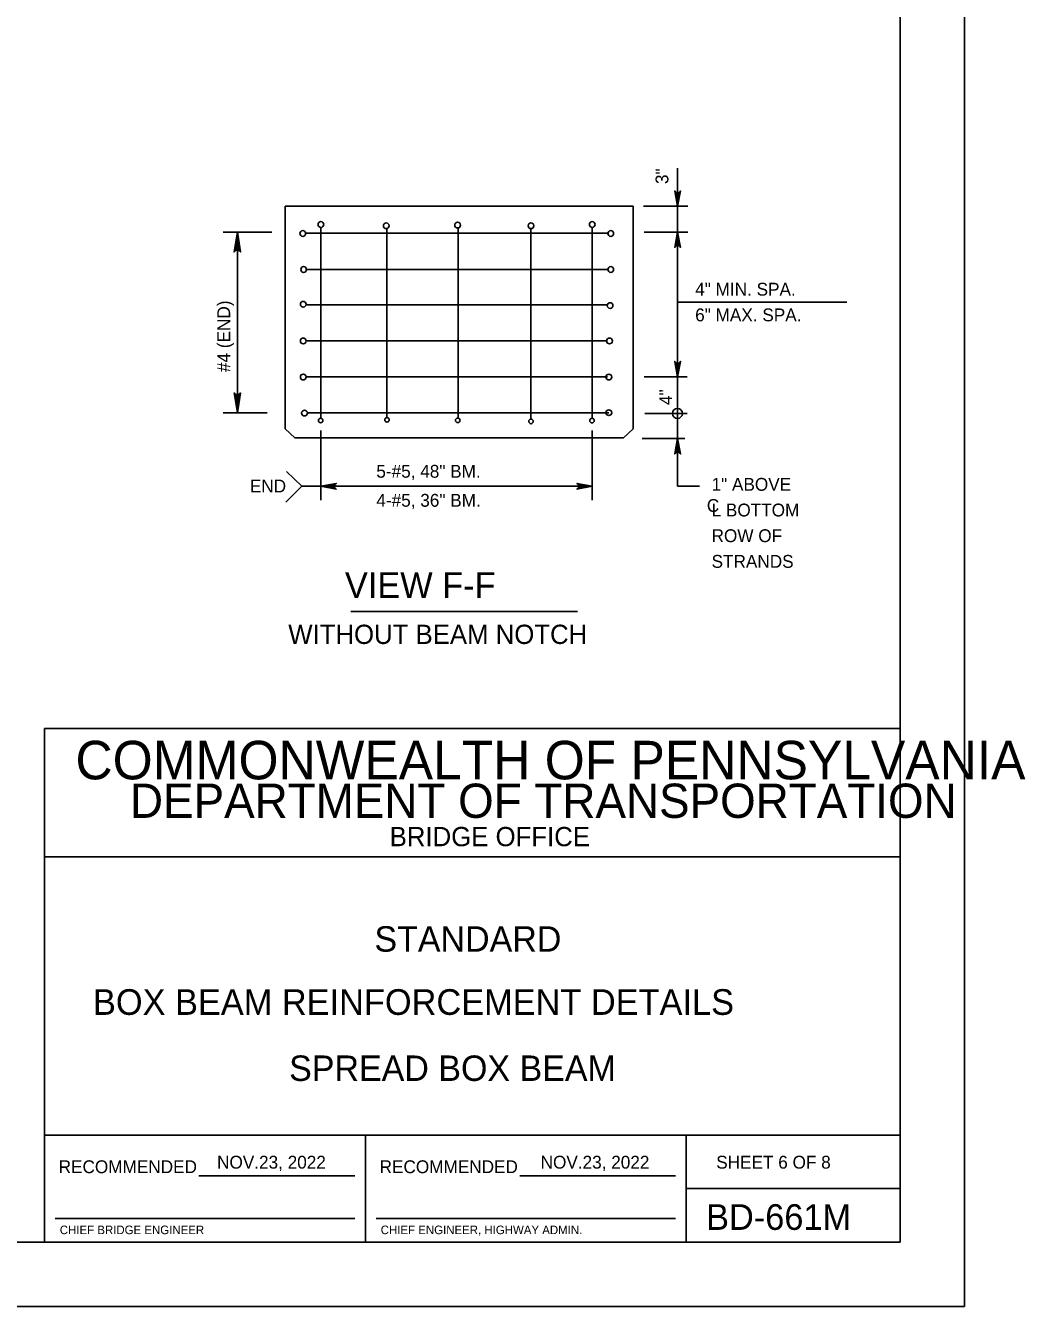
# Model space of a CAD drawing. Extents: x 639331 to 643089, y 299088 to 300975.
# Drawn here: x 642014.7 to 642248.3, y 299087.7 to 299386.9 of the extents above; entities that cross this region are included whole.
import ezdxf

# ---------------------------------------------------------------- set-up
doc = ezdxf.new("R2010")
doc.units = 0
for name, color, linetype in [('1', 7, 'Continuous'), ('DATES', 7, 'Continuous'), ('PLT-BNDY', 7, 'Continuous'), ('SIGNATORY TITLES', 7, 'Continuous')]:
    doc.layers.add(name, color=color, linetype=linetype)

msp = doc.modelspace()

# ---------------------------------------------------------------- linework, layer by layer
at = {"layer": '1'}
for p, q in [((642219.06, 299666.66), (642219.06, 299102.66)), ((642167.03, 299353.53), (642167.03, 299344.35)), ((642156.65, 299344.65), (642075.31, 299344.65)), ((642075.31, 299292.63), (642075.31, 299344.65)), ((642156.65, 299292.63), (642156.65, 299344.65)), ((642159.06, 299344.65), (642169.43, 299344.65)), ((642167.03, 299344.65), (642167.03, 299338.64)), ((642147.07, 299339.69), (642147.07, 299295.19)), ((642072.17, 299338.64), (642060.84, 299338.64)), ((642064.14, 299338.64), (642064.14, 299296.39)), ((642080.09, 299338.34), (642150.94, 299338.34)), ((642083.67, 299339.54), (642083.67, 299295.19)), ((642099.07, 299339.39), (642099.07, 299295.34)), ((642115.76, 299339.54), (642115.76, 299295.19)), ((642132.75, 299339.39), (642132.75, 299295.04)), ((642159.21, 299338.64), (642169.43, 299338.64)), ((642167.03, 299338.64), (642167.03, 299304.81)), ((642080.31, 299329.92), (642150.79, 299329.92)), ((642080.28, 299321.65), (642150.64, 299321.65)), ((642167.03, 299322.27), (642206.54, 299322.27)), ((642080.43, 299313.23), (642150.64, 299313.23)), ((642080.28, 299304.81), (642150.64, 299304.81)), ((642159.21, 299304.81), (642169.28, 299304.81)), ((642167.03, 299304.81), (642167.03, 299296.24)), ((642071.08, 299296.39), (642060.84, 299296.39)), ((642080.43, 299296.39), (642150.94, 299296.39)), ((642159.36, 299296.24), (642169.28, 299296.24)), ((642167.03, 299296.24), (642167.03, 299290.53)), ((642075.31, 299292.63), (642077.57, 299290.53)), ((642083.67, 299292.24), (642083.67, 299275.98)), ((642147.07, 299292.24), (642147.07, 299275.98)), ((642154.4, 299290.53), (642156.65, 299292.63)), ((642154.4, 299290.53), (642077.57, 299290.53)), ((642158.76, 299290.38), (642168.68, 299290.38)), ((642167.03, 299290.53), (642167.03, 299279.25)), ((642079.18, 299279.25), (642075.66, 299282.68)), ((642079.18, 299279.25), (642075.46, 299275.53)), ((642079.18, 299279.25), (642147.07, 299279.25)), ((642167.03, 299279.25), (642172.15, 299279.25)), ((642090.66, 299250.02), (642143.66, 299250.02)), ((642219.06, 299222.66), (642019.06, 299222.66)), ((642019.06, 299222.66), (642019.06, 299102.66)), ((642219.06, 299102.66), (642219.06, 299222.66)), ((642219.06, 299192.66), (642019.06, 299192.66)), ((642219.06, 299127.66), (642019.06, 299127.66)), ((642094.06, 299102.66), (642094.06, 299127.66)), ((642169.06, 299127.66), (642169.06, 299102.66)), ((642055.15, 299118.16), (642091.56, 299118.16)), ((642130.15, 299118.16), (642166.56, 299118.16)), ((642169.06, 299115.16), (642219.06, 299115.16)), ((642021.56, 299108.16), (642091.56, 299108.16)), ((642096.56, 299108.16), (642166.56, 299108.16)), ((642219.06, 299102.66), (641433.06, 299102.66)), ((642019.06, 299102.66), (642219.06, 299102.66))]:
    msp.add_line(p, q, dxfattribs=at)
for points in [[(642167.03, 299344.65), (642166.36, 299348.24), (642166.45, 299348.1), (642166.55, 299347.97), (642166.67, 299347.89), (642166.79, 299347.82), (642166.91, 299347.8), (642167.03, 299347.78), (642167.15, 299347.8), (642167.27, 299347.82), (642167.39, 299347.89), (642167.51, 299347.97), (642167.61, 299348.1), (642167.7, 299348.24), (642167.03, 299344.65), (642167.61, 299348.1), (642167.51, 299347.97), (642167.03, 299344.65), (642167.39, 299347.89), (642167.27, 299347.82), (642167.03, 299344.65), (642167.15, 299347.8), (642167.03, 299347.78), (642167.03, 299344.65), (642166.91, 299347.8), (642166.79, 299347.82), (642167.03, 299344.65), (642166.67, 299347.89), (642166.55, 299347.97), (642167.03, 299344.65), (642166.45, 299348.1)], [(642063.58, 299334.22), (642063.9, 299334.38), (642064.14, 299338.64), (642063.58, 299334.22), (642063.39, 299333.99), (642064.14, 299338.64), (642064.35, 299334.38), (642064.66, 299334.23), (642064.14, 299338.64), (642064.88, 299333.99), (642064.66, 299334.23)], [(642167.03, 299338.64), (642167.7, 299335.05), (642167.61, 299335.19), (642167.51, 299335.33), (642167.39, 299335.4), (642167.27, 299335.47), (642167.15, 299335.49), (642167.03, 299335.51), (642166.91, 299335.49), (642166.79, 299335.47), (642166.67, 299335.4), (642166.55, 299335.33), (642166.45, 299335.19), (642166.36, 299335.05), (642167.03, 299338.64), (642166.45, 299335.19), (642166.55, 299335.33), (642167.03, 299338.64), (642166.67, 299335.4), (642166.79, 299335.47), (642167.03, 299338.64), (642166.91, 299335.49), (642167.03, 299335.51), (642167.03, 299338.64), (642167.15, 299335.49), (642167.27, 299335.47), (642167.03, 299338.64), (642167.39, 299335.4), (642167.51, 299335.33), (642167.03, 299338.64), (642167.61, 299335.19)], [(642167.03, 299304.81), (642166.36, 299308.4), (642166.45, 299308.26), (642166.55, 299308.12), (642166.67, 299308.05), (642166.79, 299307.98), (642166.91, 299307.96), (642167.03, 299307.94), (642167.15, 299307.96), (642167.27, 299307.98), (642167.39, 299308.05), (642167.51, 299308.12), (642167.61, 299308.26), (642167.7, 299308.4), (642167.03, 299304.81), (642167.61, 299308.26), (642167.51, 299308.12), (642167.03, 299304.81), (642167.39, 299308.05), (642167.27, 299307.98), (642167.03, 299304.81), (642167.15, 299307.96), (642167.03, 299307.94), (642167.03, 299304.81), (642166.91, 299307.96), (642166.79, 299307.98), (642167.03, 299304.81), (642166.67, 299308.05), (642166.55, 299308.12), (642167.03, 299304.81), (642166.45, 299308.26)], [(642064.69, 299300.82), (642064.37, 299300.65), (642064.14, 299296.39), (642064.69, 299300.82), (642064.89, 299301.04), (642064.14, 299296.39), (642063.93, 299300.65), (642063.61, 299300.8), (642064.14, 299296.39), (642063.4, 299301.04), (642063.61, 299300.8)], [(642167.03, 299290.38), (642167.7, 299286.79), (642167.61, 299286.93), (642167.51, 299287.07), (642167.39, 299287.14), (642167.27, 299287.21), (642167.15, 299287.23), (642167.03, 299287.25), (642166.91, 299287.23), (642166.79, 299287.21), (642166.67, 299287.14), (642166.55, 299287.07), (642166.45, 299286.93), (642166.36, 299286.79), (642167.03, 299290.38), (642166.45, 299286.93), (642166.55, 299287.07), (642167.03, 299290.38), (642166.67, 299287.14), (642166.79, 299287.21), (642167.03, 299290.38), (642166.91, 299287.23), (642167.03, 299287.25), (642167.03, 299290.38), (642167.15, 299287.23), (642167.27, 299287.21), (642167.03, 299290.38), (642167.39, 299287.14), (642167.51, 299287.07), (642167.03, 299290.38), (642167.61, 299286.93)], [(642083.67, 299279.25), (642087.26, 299279.93), (642087.12, 299279.83), (642086.98, 299279.73), (642086.91, 299279.61), (642086.84, 299279.49), (642086.82, 299279.37), (642086.79, 299279.25), (642086.82, 299279.13), (642086.84, 299279.01), (642086.91, 299278.89), (642086.98, 299278.77), (642087.12, 299278.68), (642087.26, 299278.58), (642083.67, 299279.25), (642087.12, 299278.68), (642086.98, 299278.77), (642083.67, 299279.25), (642086.91, 299278.89), (642086.84, 299279.01), (642083.67, 299279.25), (642086.82, 299279.13), (642086.79, 299279.25), (642083.67, 299279.25), (642086.82, 299279.37), (642086.84, 299279.49), (642083.67, 299279.25), (642086.91, 299279.61), (642086.98, 299279.73), (642083.67, 299279.25), (642087.12, 299279.83)], [(642147.07, 299279.25), (642143.48, 299278.58), (642143.62, 299278.68), (642143.75, 299278.77), (642143.83, 299278.89), (642143.9, 299279.01), (642143.92, 299279.13), (642143.94, 299279.25), (642143.92, 299279.37), (642143.9, 299279.49), (642143.83, 299279.61), (642143.75, 299279.73), (642143.62, 299279.83), (642143.48, 299279.93), (642147.07, 299279.25), (642143.62, 299279.83), (642143.75, 299279.73), (642147.07, 299279.25), (642143.83, 299279.61), (642143.9, 299279.49), (642147.07, 299279.25), (642143.92, 299279.37), (642143.94, 299279.25), (642147.07, 299279.25), (642143.92, 299279.13), (642143.9, 299279.01), (642147.07, 299279.25), (642143.83, 299278.89), (642143.75, 299278.77), (642147.07, 299279.25), (642143.62, 299278.68)]]:
    msp.add_lwpolyline(points, dxfattribs=at)
for centre, radius in [((642083.68, 299340.41), 0.672), ((642098.93, 299340.11), 0.672), ((642115.62, 299340.26), 0.672), ((642132.76, 299340.11), 0.672), ((642147.08, 299340.41), 0.672), ((642079.42, 299338.3), 0.672), ((642151.4, 299338.3), 0.672), ((642079.64, 299329.88), 0.672), ((642151.4, 299329.88), 0.672), ((642079.54, 299321.76), 0.672), ((642151.25, 299321.46), 0.672), ((642079.54, 299313.19), 0.672), ((642151.1, 299313.19), 0.672), ((642079.54, 299304.77), 0.672), ((642150.95, 299304.77), 0.672), ((642079.84, 299296.35), 0.672), ((642083.61, 299294.62), 0.538), ((642099.11, 299294.76), 0.538), ((642115.64, 299294.65), 0.538), ((642132.77, 299294.41), 0.538), ((642147.02, 299294.6), 0.538), ((642150.95, 299296.44), 0.672), ((642166.98, 299296.27), 1.18)]:
    msp.add_circle(centre, radius, dxfattribs=at)
at = {"layer": 'PLT-BNDY'}
msp.add_lwpolyline([(641393.06, 299681.66), (642234.06, 299681.66), (642234.06, 299087.66), (641393.06, 299087.66)], close=True, dxfattribs=at)

# ---------------------------------------------------------------- texts
at = {"layer": '1'}
for s, p in [('3"', (642164.87, 299349.85)), ('#4 (END)', (642062.47, 299305.93)), ('4"', (642165.73, 299298.24))]:
    msp.add_text(s, height=3, rotation=90, dxfattribs=at).set_placement(p)
for s, height, p in [('4" MIN. SPA.', 3, (642171.13, 299323.78)), ('6" MAX. SPA.', 3, (642171.13, 299317.78)), ('5-#5, 48" BM.', 3, (642096.62, 299281.25)), ('END', 3, (642067.06, 299277.8)), ('1" ABOVE', 3, (642174.96, 299278.2)), ('4-#5, 36" BM.', 3, (642096.63, 299274.47)), ('C', 3, (642173.85, 299273.25)), ('L BOTTOM', 3, (642174.96, 299272.2)), ('ROW OF', 3, (642174.96, 299266.2)), ('STRANDS', 3, (642174.96, 299260.2)), (' VIEW F-F', 6, (642087.05, 299253.15)), ('WITHOUT BEAM NOTCH', 4.5, (642076.04, 299242.41)), ('COMMONWEALTH OF PENNSYLVANIA', 9, (642026.31, 299210.78)), ('DEPARTMENT OF TRANSPORTATION', 8.0002, (642039.06, 299201.78)), ('BRIDGE OFFICE', 4.5, (642099.74, 299195.16)), ('STANDARD', 5.939, (642096.18, 299170.53)), ('BOX BEAM REINFORCEMENT DETAILS', 6, (642030.41, 299155.76)), ('SPREAD BOX BEAM', 5.9393, (642076.24, 299140.33)), ('RECOMMENDED', 3, (642022.39, 299118.78)), ('RECOMMENDED', 3, (642097.39, 299118.78)), ('SHEET 6 OF 8', 3, (642176.05, 299119.84)), ('BD-661M', 6, (642173.68, 299105.53))]:
    msp.add_text(s, height=height, dxfattribs=at).set_placement(p)
at = {"layer": 'DATES'}
for p in [(642059.4, 299119.84), (642135.01, 299119.84)]:
    msp.add_text('NOV.23, 2022', height=3, dxfattribs=at).set_placement(p)
at = {"layer": 'SIGNATORY TITLES'}
for s, p in [('CHIEF BRIDGE ENGINEER', (642022.65, 299104.53)), ('CHIEF ENGINEER, HIGHWAY ADMIN.', (642097.65, 299104.53))]:
    msp.add_text(s, height=2, dxfattribs=at).set_placement(p)

doc.saveas('drawing.dxf')
